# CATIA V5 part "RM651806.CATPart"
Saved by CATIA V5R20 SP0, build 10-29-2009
Part number: RM651806
Revision: ANY
Definition: UNKNOWN
Nomenclature: RM651806
Source: Unknown
Bounding box of the stored display mesh (mm): x -8 to 57, y -8 to 8, z 0 to 3
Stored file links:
  C:\Users\Utente\Desktop\IO LAVORO\3D X SITO CF\CUMSA\3D files RM.651608\RM 651608\RM651806.CATPart
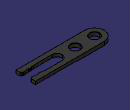
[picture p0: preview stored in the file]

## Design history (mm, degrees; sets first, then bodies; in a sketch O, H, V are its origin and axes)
Body1 "Chaflán1" (main body)
  Solid1: solid without history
